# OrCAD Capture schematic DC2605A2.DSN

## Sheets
1 PAGE3: size B; title: HIGH EFFICIENCY, POLY-PHASE SYNCHRONOUS BUCK; rev: 2; company: TM; note: CONVERTER WITH POWER SYSTEM MANAGEMENT
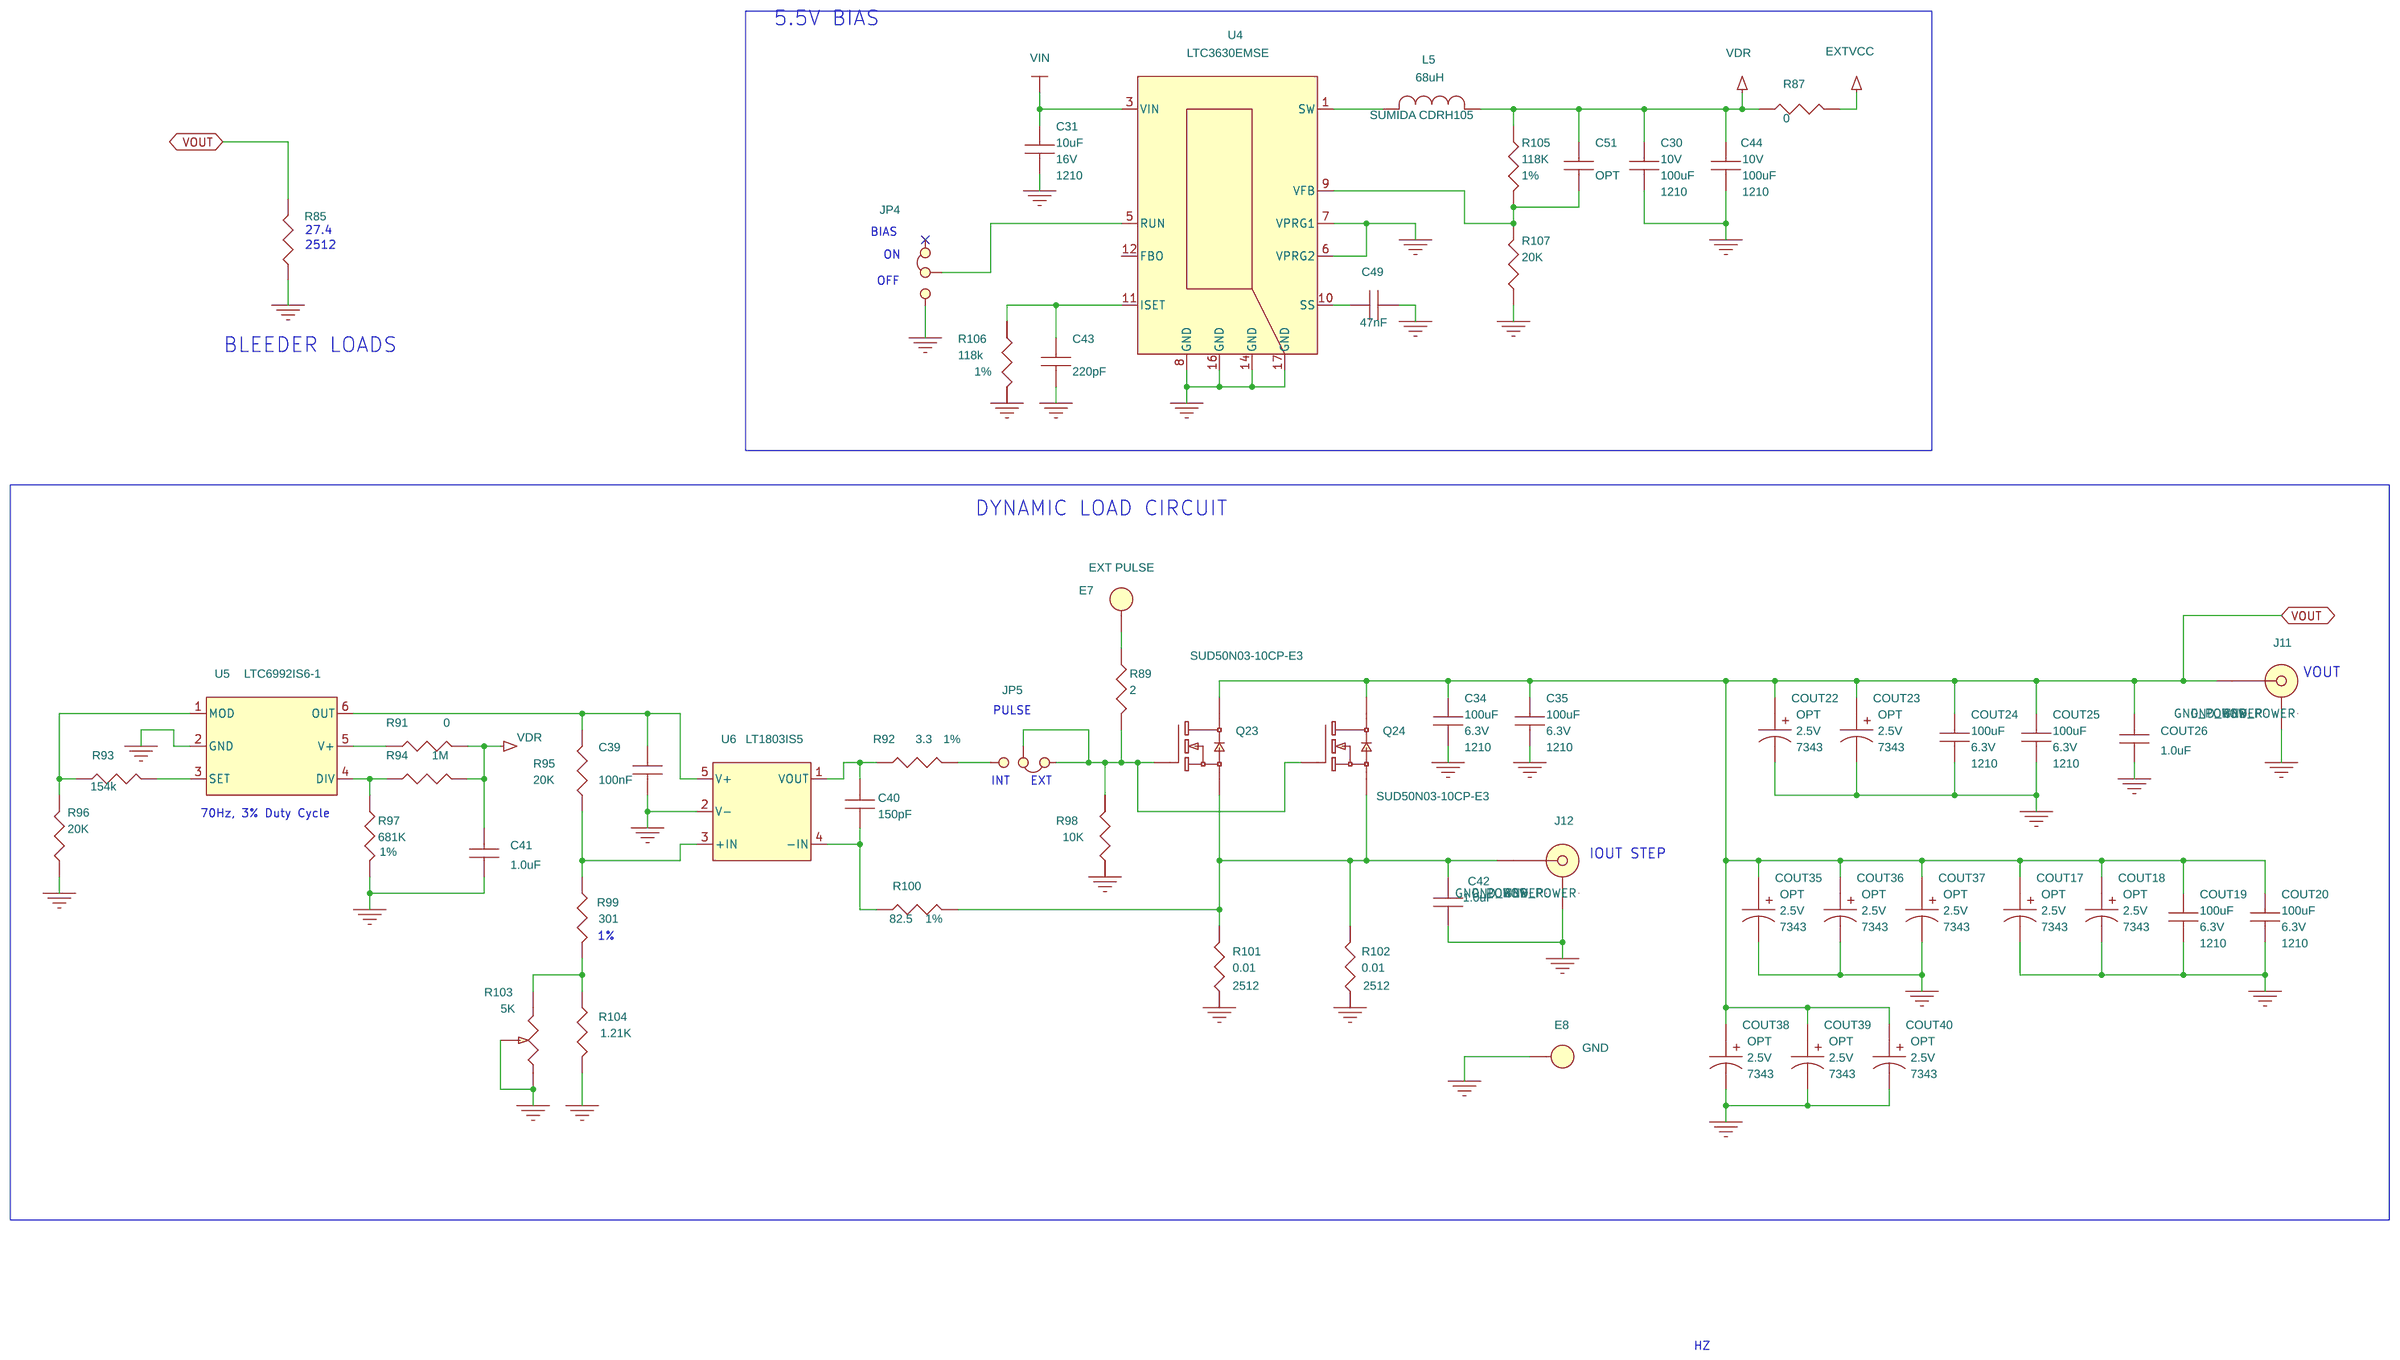
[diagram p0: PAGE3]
2 PAGE1: size Custom
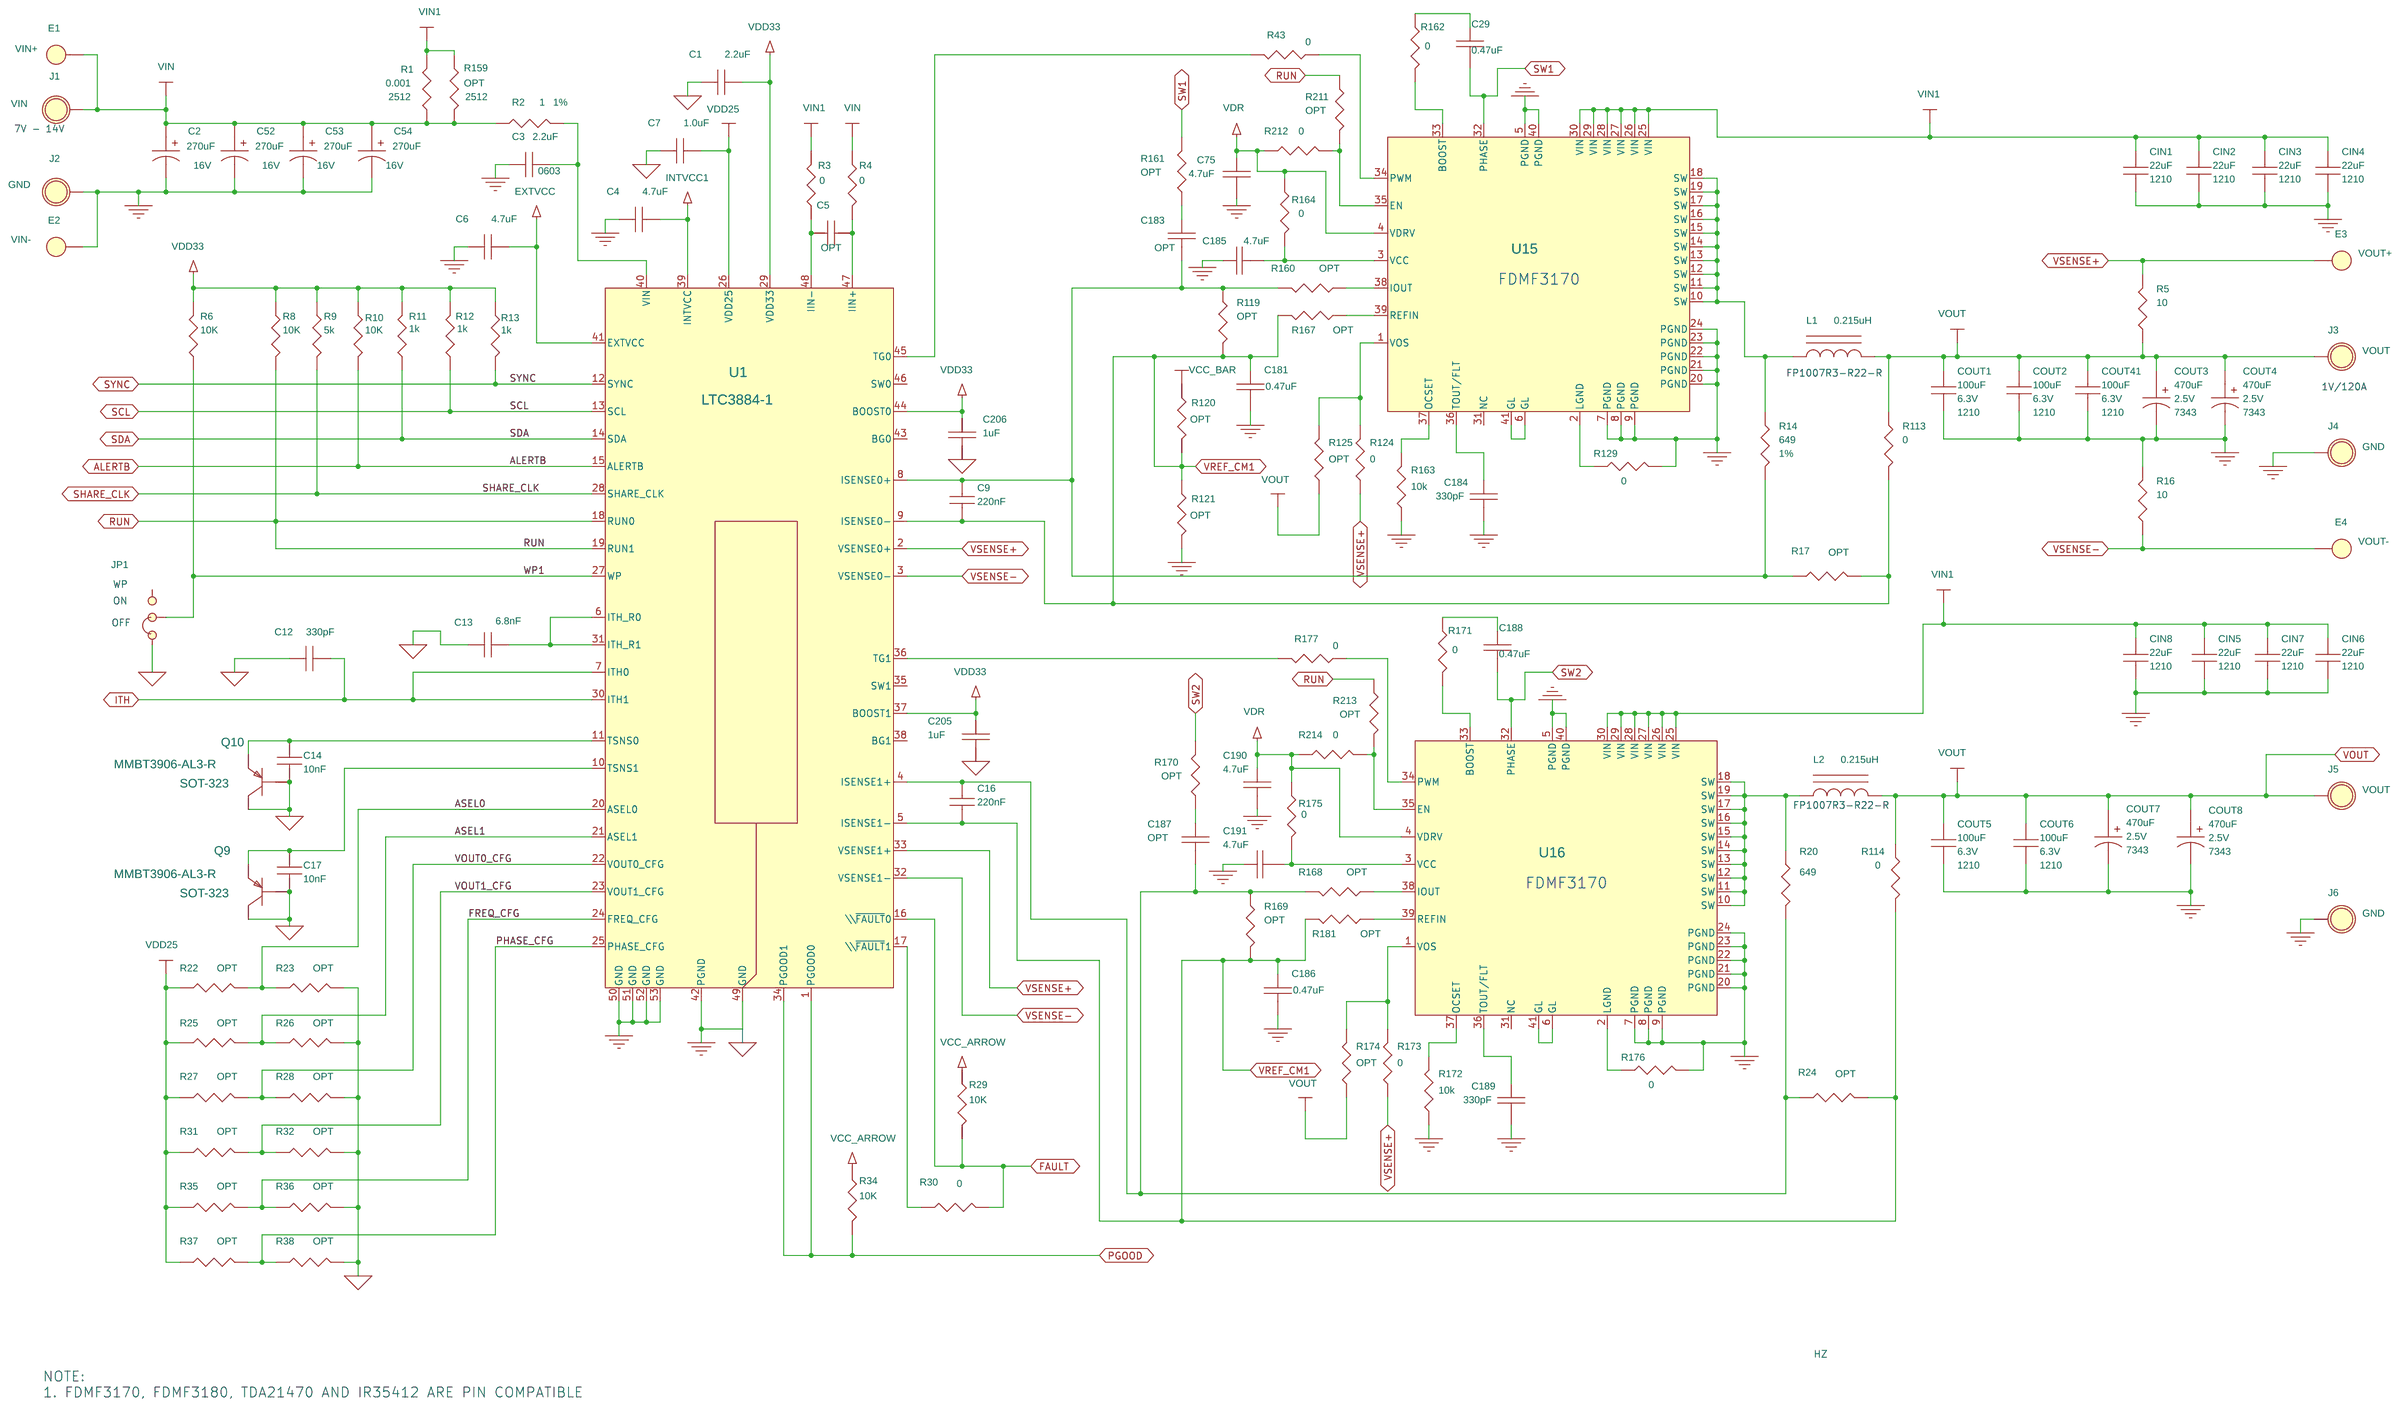
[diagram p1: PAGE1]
3 PAGE2: size Custom
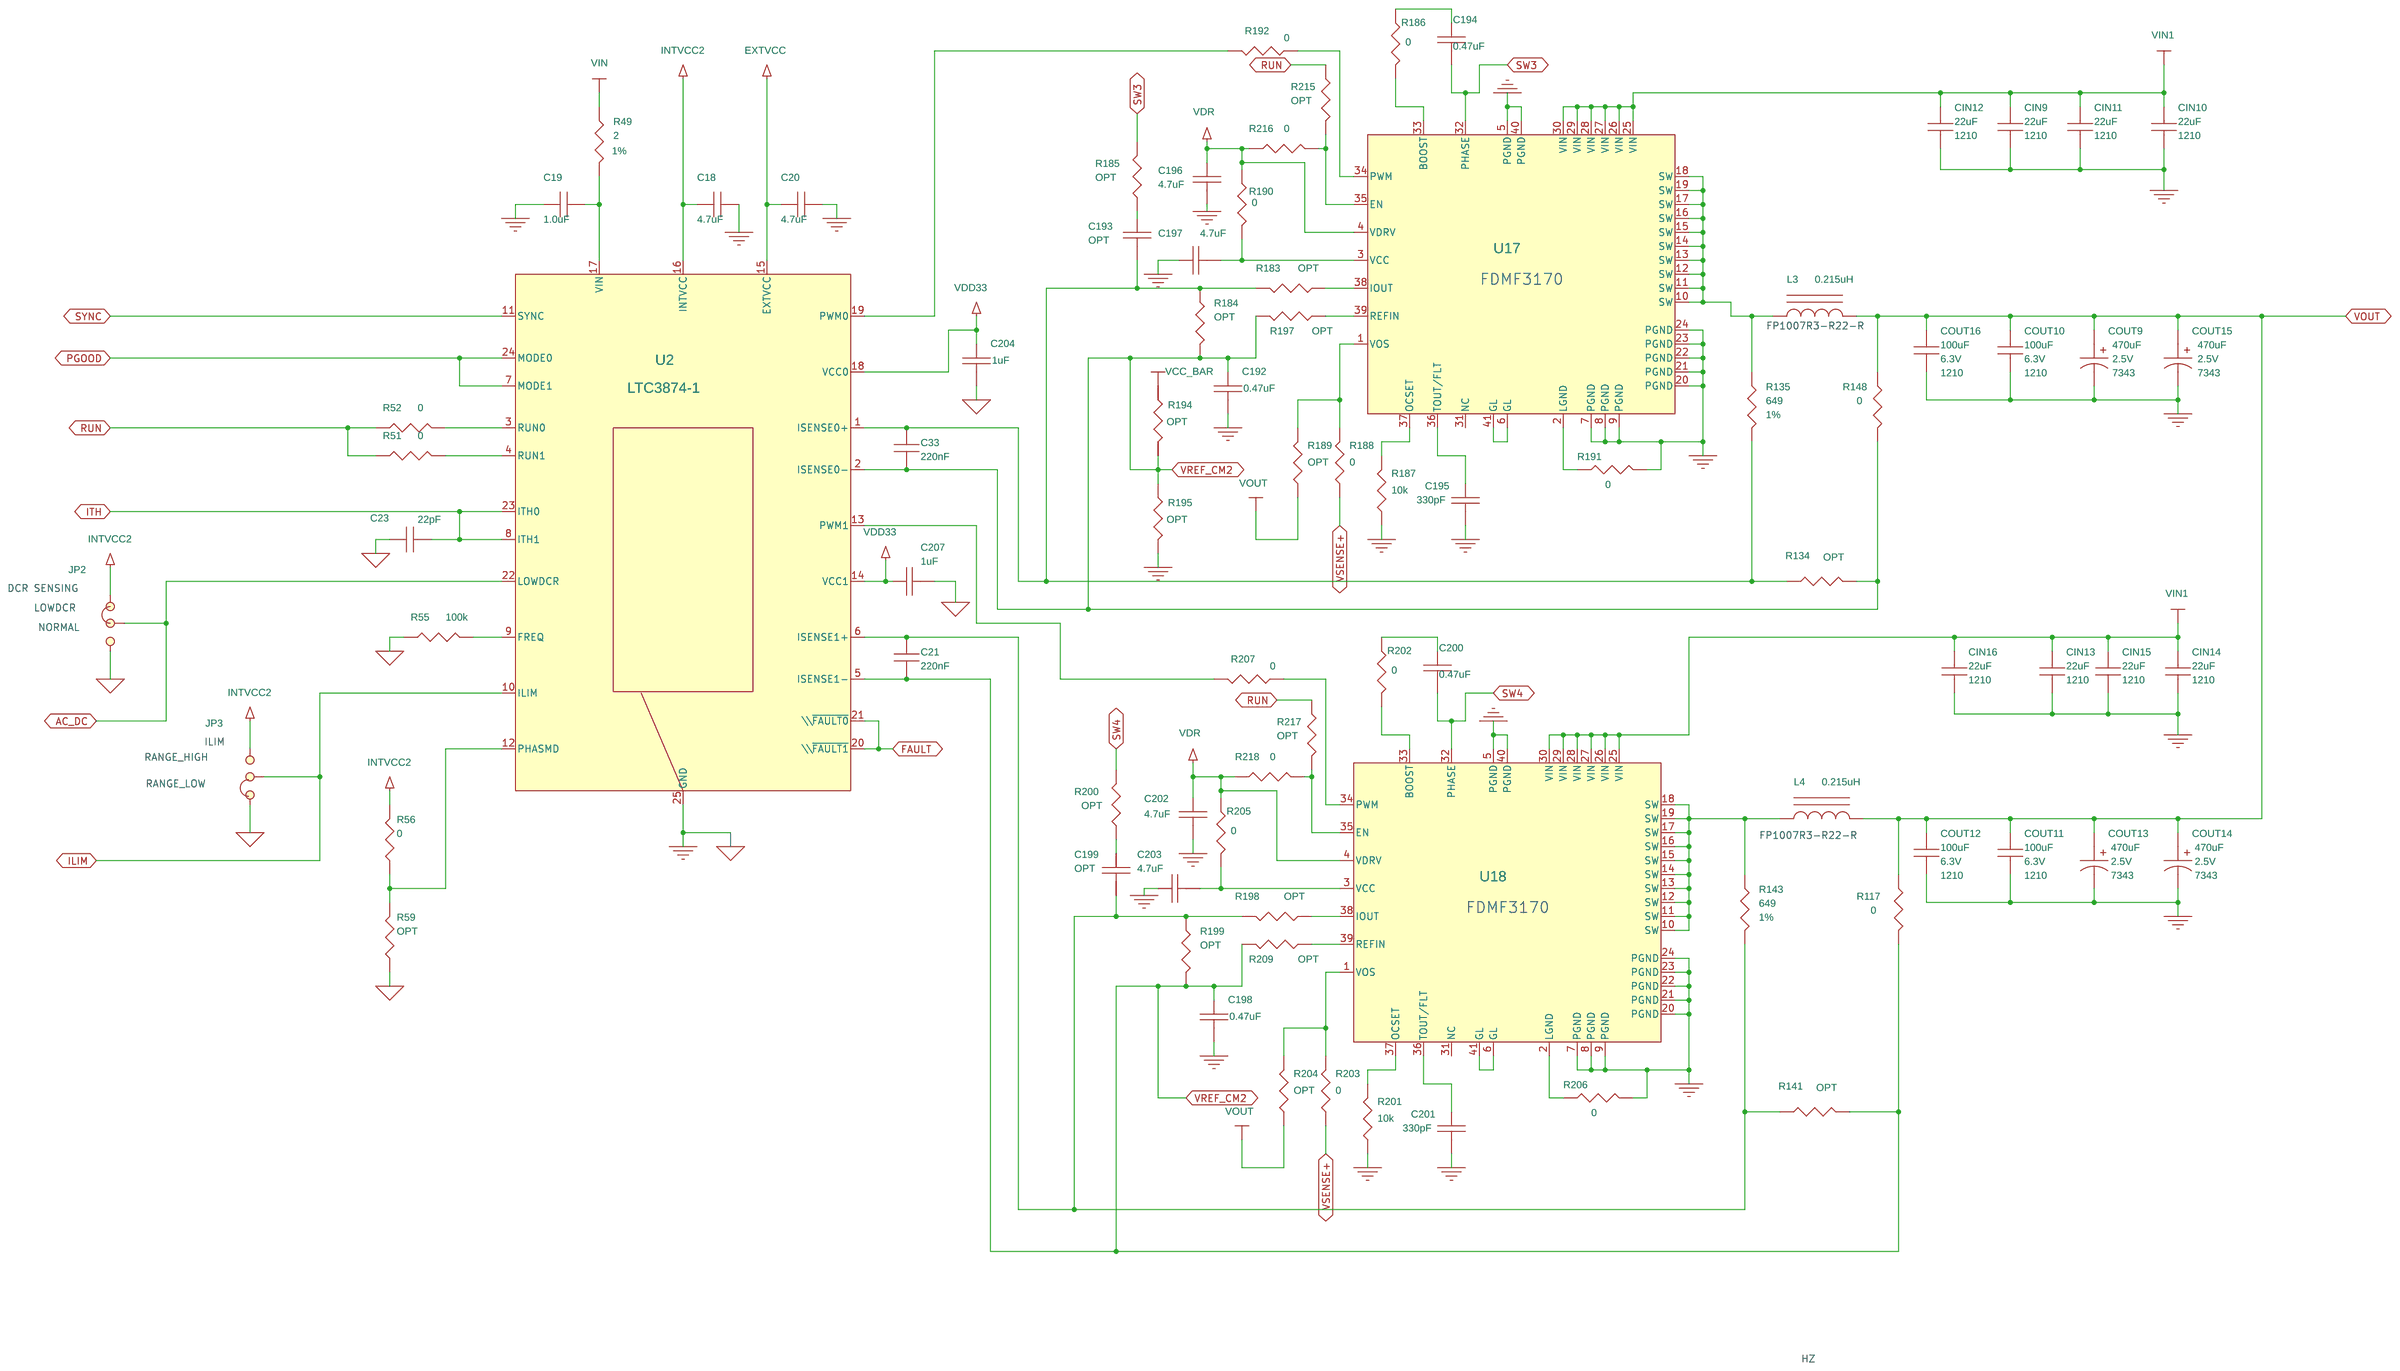
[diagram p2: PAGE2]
4 PAGE4: size B
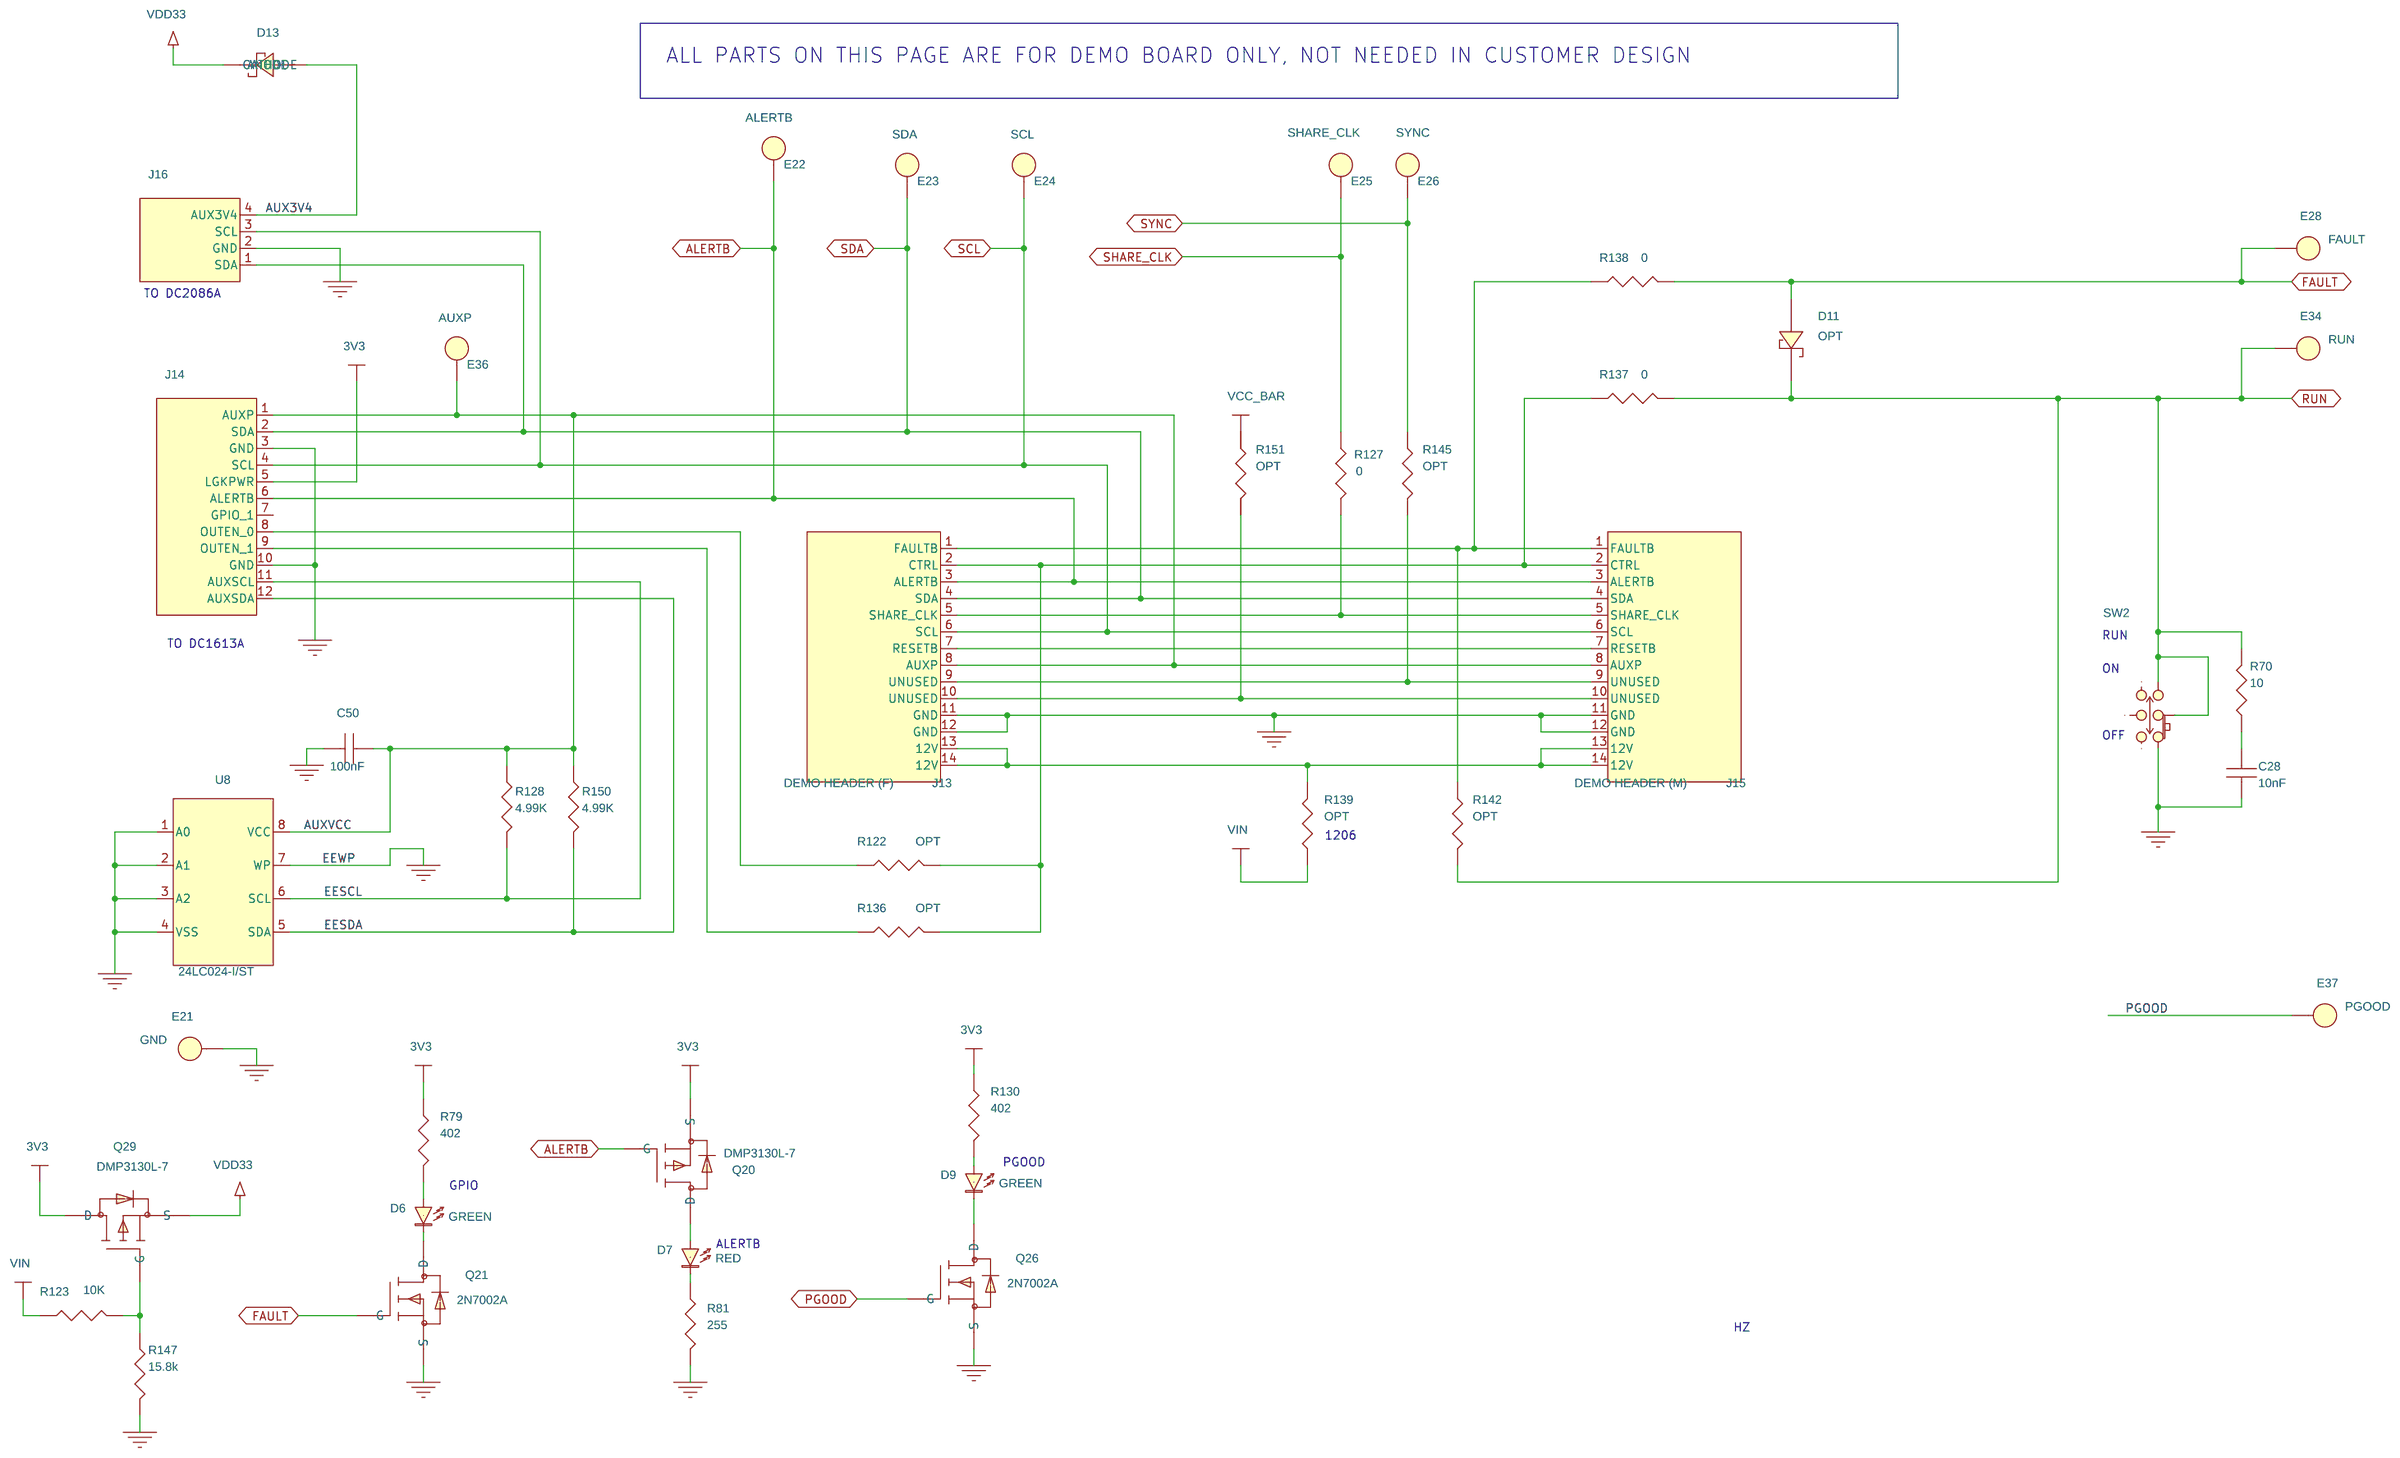
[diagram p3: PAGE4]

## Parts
sheet PAGE1
C1  2.2uF  [0603]
C2  270uF  [CAP\SAN\OSCON\SVF12]
C3  2.2uF  [0603]
C4  4.7uF  [0603]
C5  OPT  [0603]
C6  4.7uF  [0603]
C7  1.0uF  [0603]
C9  220nF  [0603]
C12  330pF  [0603]
C13  6.8nF  [0603]
C14  10nF  [0603]
C16  220nF  [0603]
C17  10nF  [0603]
C29  0.47uF  [0402]
C52  270uF  [CAP\SAN\OSCON\SVF12]
C53  270uF  [CAP\SAN\OSCON\SVF12]
C54  270uF  [CAP\SAN\OSCON\SVF12]
C75  4.7uF  [0402]
C181  0.47uF  [0402]
C183  OPT  [0402]
C184  330pF  [0402]
C185  4.7uF  [0402]
C186  0.47uF  [0402]
C187  OPT  [0402]
C188  0.47uF  [0402]
C189  330pF  [0402]
C190  4.7uF  [0402]
C191  4.7uF  [0402]
C205  1uF  [0402]
C206  1uF  [0402]
CIN1  22uF  [1210]
CIN2  22uF  [1210]
CIN3  22uF  [1210]
CIN4  22uF  [1210]
CIN5  22uF  [1210]
CIN6  22uF  [1210]
CIN7  22uF  [1210]
CIN8  22uF  [1210]
COUT1  100uF  [1210]
COUT2  100uF  [1210]
COUT3  470uF  [7343]
COUT4  470uF  [7343]
COUT5  100uF  [1210]
COUT6  100uF  [1210]
COUT7  470uF  [7343]
COUT8  470uF  [7343]
COUT41  100uF  [1210]
E1  VIN+  [TP\MMX\2501-2]
E2  VIN-  [TP\MMX\2501-2]
E3  VOUT+  [TP\MMX\2501-2]
E4  VOUT-  [TP\MMX\2501-2]
J1  BANANA SMALL  [CON\LUG\10]
J2  BANANA SMALL  [CON\LUG\10]
J3  BANANA SMALL  [CON\LUG\10]
J4  BANANA SMALL  [CON\LUG\10]
J5  BANANA SMALL  [CON\LUG\10]
J6  BANANA SMALL  [CON\LUG\10]
JP1  JP3X1/079\NO\12  [SIP\3P\2MM]
L1  0.215uH  [fp1007]
L2  0.215uH  [fp1007]
Q9  MMBT3906-AL3-R  [SOT-323]
Q10  MMBT3906-AL3-R  [SOT-323]
R1  0.001  [2512]
R2  1  [0603]
R3  0  [0603]
R4  0  [0603]
R5  10  [0603]
R6  10K  [0603]
R8  10K  [0603]
R9  5k  [0603]
R10  10K  [0603]
R11  1k  [0603]
R12  1k  [0603]
R13  1k  [0603]
R14  649  [0603]
R16  10  [0603]
R17  OPT  [0603]
R20  649  [0603]
R22  OPT  [0603]
R23  OPT  [0603]
R24  OPT  [0603]
R25  OPT  [0603]
R26  OPT  [0603]
R27  OPT  [0603]
R28  OPT  [0603]
R29  10K  [0603]
R30  0  [0603]
R31  OPT  [0603]
R32  OPT  [0603]
R34  10K  [0603]
R35  OPT  [0603]
R36  OPT  [0603]
R37  OPT  [0603]
R38  OPT  [0603]
R43  0  [0402]
R113  0  [0603]
R114  0  [0603]
R119  OPT  [0402]
R120  OPT  [0402]
R121  OPT  [0402]
R124  0  [0402]
R125  OPT  [0402]
R129  0  [0402]
R159  OPT  [2512]
R160  OPT  [0402]
R161  OPT  [0402]
R162  0  [0402]
R163  10k  [0402]
R164  0  [0402]
R167  OPT  [0402]
R168  OPT  [0402]
R169  OPT  [0402]
R170  OPT  [0402]
R171  0  [0402]
R172  10k  [0402]
R173  0  [0402]
R174  OPT  [0402]
R175  0  [0402]
R176  0  [0402]
R177  0  [0402]
R181  OPT  [0402]
R211  OPT  [0402]
R212  0  [0402]
R213  OPT  [0402]
R214  0  [0402]
U1  LTC3884-1  [CQFN-48-5MMX6MM]
U15  LTC2248CUH  [IR35411]
U16  LTC2248CUH  [IR35411]
XJP1  SHUNT  [NONE]
sheet PAGE2
C18  4.7uF  [0603]
C19  1.0uF  [0603]
C20  4.7uF  [0603]
C21  220nF  [0603]
C23  22pF  [0603]
C33  220nF  [0603]
C192  0.47uF  [0402]
C193  OPT  [0402]
C194  0.47uF  [0402]
C195  330pF  [0402]
C196  4.7uF  [0402]
C197  4.7uF  [0402]
C198  0.47uF  [0402]
C199  OPT  [0402]
C200  0.47uF  [0402]
C201  330pF  [0402]
C202  4.7uF  [0402]
C203  4.7uF  [0402]
C204  1uF  [0402]
C207  1uF  [0402]
CIN9  22uF  [1210]
CIN10  22uF  [1210]
CIN11  22uF  [1210]
CIN12  22uF  [1210]
CIN13  22uF  [1210]
CIN14  22uF  [1210]
CIN15  22uF  [1210]
CIN16  22uF  [1210]
COUT9  470uF  [7343]
COUT10  100uF  [1210]
COUT11  100uF  [1210]
COUT12  100uF  [1210]
COUT13  470uF  [7343]
COUT14  470uF  [7343]
COUT15  470uF  [7343]
COUT16  100uF  [1210]
JP2  JP3X1/079\NO\12  [SIP\3P\2MM]
JP3  JP3X1/079\NO\12  [SIP\3P\2MM]
L3  0.215uH  [fp1007]
L4  0.215uH  [fp1007]
R49  2  [0603]
R51  0  [0603]
R52  0  [0603]
R55  100k  [0603]
R56  0  [0603]
R59  OPT  [0603]
R117  0  [0603]
R134  OPT  [0603]
R135  649  [0603]
R141  OPT  [0603]
R143  649  [0603]
R148  0  [0603]
R183  OPT  [0402]
R184  OPT  [0402]
R185  OPT  [0402]
R186  0  [0402]
R187  10k  [0402]
R188  0  [0402]
R189  OPT  [0402]
R190  0  [0402]
R191  0  [0402]
R192  0  [0402]
R194  OPT  [0402]
R195  OPT  [0402]
R197  OPT  [0402]
R198  OPT  [0402]
R199  OPT  [0402]
R200  OPT  [0402]
R201  10k  [0402]
R202  0  [0402]
R203  0  [0402]
R204  OPT  [0402]
R205  0  [0402]
R206  0  [0402]
R207  0  [0402]
R209  OPT  [0402]
R215  OPT  [0402]
R216  0  [0402]
R217  OPT  [0402]
R218  0  [0402]
U2  LTC3874-1  [UF_24_4MMX4MM]
U17  LTC2248CUH  [IR35411]
U18  LTC2248CUH  [IR35411]
XJP2  SHUNT  [NONE]
XJP3  SHUNT  [NONE]
sheet PAGE3
C30  100uF  [1210]
C31  10uF  [1210]
C34  100uF  [1210]
C35  100uF  [1210]
C39  100nF  [0603]
C40  150pF  [0603]
C41  1.0uF  [0603]
C42  1.0uF  [0603]
C43  220pF  [0603]
C44  100uF  [1210]
C49  47nF  [0603]
C51  OPT  [0603]
COUT17  OPT  [7343]
COUT18  OPT  [7343]
COUT19  100uF  [1210]
COUT20  100uF  [1210]
COUT22  OPT  [7343]
COUT23  OPT  [7343]
COUT24  100uF  [1210]
COUT25  100uF  [1210]
COUT26  1.0uF  [0603]
COUT35  OPT  [7343]
COUT36  OPT  [7343]
COUT37  OPT  [7343]
COUT38  OPT  [7343]
COUT39  OPT  [7343]
COUT40  OPT  [7343]
E7  EXT PULSE  [TP\MMX\2501-2]
E8  GND  [TP\MMX\2501-2]
J11  XXX  [BNC]
J12  XXX  [BNC]
JP4  JP3X1/079\NO\12  [SIP\3P\2MM]
JP5  JP3X1/079\NO\12  [SIP\3P\2MM]
L5  68uH  [IND\SUMIDA\CDRH105R\12X12]
Q23  SUD50N03-10CP-E3  [TO-252]
Q24  SUD50N03-10CP-E3  [TO-252]
R85  OPT  [2512]
R87  0  [0603]
R89  2  [0603]
R91  0  [0603]
R92  3.3  [0603]
R93  154k  [0603]
R94  1M  [0603]
R95  20K  [0603]
R96  20K  [0603]
R97  681K  [0603]
R98  10K  [0603]
R99  301  [0603]
R100  82.5  [0603]
R101  0.01  [2512]
R102  0.01  [2512]
R103  5K  [BOURNS_3386P]
R104  1.21K  [0603]
R105  118K  [0603]
R106  118k  [0603]
R107  20K  [0603]
U4  LTC3630EMSE  [MSE-16L(12)]
U5  LTC6992IS6-1  [LT_S6]
U6  LT1803IS5  [LT_S5]
XJP4  SHUNT  [NONE]
XJP5  SHUNT  [NONE]
sheet PAGE4
C28  10nF  [0603]
C50  100nF  [0603]
D6  GREEN  [LED_0603]
D7  RED  [LED_0603]
D9  GREEN  [LED_0603]
D11  OPT  [SOD323]
D13  DIODE SCHOTTKY  [SOD882]
E21  GND  [TP\MMX\2501-2]
E22  ALERTB  [TP\MMX\2501-2]
E23  SDA  [TP\MMX\2501-2]
E24  SCL  [TP\MMX\2501-2]
E25  SHARE_CLK  [TP\MMX\2501-2]
E26  SYNC  [TP\MMX\2501-2]
E28  FAULT  [TP\MMX\2501-2]
E34  RUN  [TP\MMX\2501-2]
E36  AUXP  [TP\MMX\2501-2]
E37  PGOOD  [TP\MMX\2501-2]
J13  DEMO HEADER (F)  [NPPN072FJFN-RC]
J14  HD2X6-079  [HD2X6-079-MOLEX]
J15  DEMO HEADER (M)  [NPPN072FJFN]
J16  HD2X6-079-PMBUS_0  [CON\HRS\DF3A-4P-2DSA]
Q20  DMP3130L-7  [SOT23]
Q21  2N7002A  [SOT23]
Q26  2N7002A  [SOT23]
Q29  DMP3130L-7  [SOT23]
R70  10  [0603]
R79  402  [0603]
R81  255  [0603]
R122  OPT  [0603]
R123  10K  [0603]
R127  0  [0603]
R128  4.99K  [0603]
R130  402  [0603]
R136  OPT  [0603]
R137  0  [0603]
R138  0  [0603]
R139  OPT  [1206]
R142  OPT  [0603]
R145  OPT  [0603]
R147  15.8k  [0603]
R150  4.99K  [0603]
R151  OPT  [0603]
SW2  JP3X1/079\NO\12  [JS202011]
U8  24LC024-I/ST  [TSSOP-8_4.4MM]

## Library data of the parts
C1 = CAP_NP: CAP, 0603 2.2uF 20% 6.3V X5R; Part Number: TAIYO YUDEN JMK105BJ225MV-T; Volts/Amps/Watts: 50V
C2 C52-C54 = CAPR12X5_0: CAP, 270uF 20% 16V OSCON; Component: cap; Manufacturer: SANYO; Part Number: PANASONIC 16SVPC270M; Tolerance: 20%; Type: OS-CON; Volts/Amps/Watts: 16V
C3 = CAP_NP_0: CAP, 0805 2.2uF 10% 16V X7R; Part Number: MURATA GRM21BR71C225KA12L; VOLTAGE: 16V
C4 C6 C18 C20 = CAP_NP: CAP, 0603 4.7uF 10% 10V X5R; Part Number: AVX 0603ZD475KAT2A
C5 C51 = CAP_NP: CAP, 0603 OPTION; Part Number: OPTION
C7 C19 C41 COUT26 = CAP_NP: CAP, 0603 1uF 20% 25V X5R; Part Number: AVX 06033D105KAT2A
C9 C16 C21 C33 = CAP_NP: CAP, 0603 220nF 10% 25V X7R; Part Number: TDK C1608X7R1E224K
C12 = CAP_NP: CAP, 0603 330pF 5% 50V C0G; Part Number: MURATA GRM1885C1H331JD01D
C13 = CAP_NP: CAP, 0603 6.8nF 10% 50V X7R; Part Number: MURATA GRM188R71H682KA01B
C14 C17 C28 = CAP_NP: CAP, 0603 10nF 10% 25V X7R; Part Number: AVX 06033C103KAT2A
C29 C183 C187 C188 C193 C194 C199 C200 C205-C207 = CAP_4: CAP, 0402 0.47uF 10% 16V X5R; Component: cap; Manufacturer: Taiyo Yuden; Manufacturer P/N: LMK212B7475KG-T; Part Number: AVX 0402YD473JAT; Tolerance: 10%; Type: cer 0805 X7R; Vendor: Digikey; Vendor P/N: 587-1442-1-ND; Volts/Amps/Watts: 10V
C75 C185 C190 C191 C196 C197 C202 C203 = CAP_4: CAP, 0603 4.7uF 20% 10V X5R; Component: cap; Manufacturer: Taiyo Yuden; Manufacturer P/N: LMK212B7475KG-T; Part Number: TAIYO YUDEN LMK107BJ475KA-T; Tolerance: 10%; Type: cer 0805 X7R; Vendor: Digikey; Vendor P/N: 587-1442-1-ND; Volts/Amps/Watts: 10V
C181 C186 C192 C198 C204 = CAP_3: CAP, 0402 0.1uF 10% 16V X7R; Manufacturer: TDK; Manufacturer P/N: C1608X7R1H104K; Part Number: AVX 0402YC103KAT2A; Tolerance: 10%; Type: cer 0603 X7R; Vendor: Digikey; Vendor P/N: 445-1314-1-ND; Volts/Amps/Watts: 16V
C184 C189 C195 C201 = CAP_4: CAP, 0402 0.1uF 10% 16V X7R; Component: cap; Manufacturer: Taiyo Yuden; Manufacturer P/N: LMK212B7475KG-T; Part Number: AVX 0402YC103KAT2A; Tolerance: 10%; Type: cer 0805 X7R; Vendor: Digikey; Vendor P/N: 587-1442-1-ND; Volts/Amps/Watts: 16V
CIN1-CIN16 = CAP_NP_0: CAP, 1210 22uF 10% 25V X7R; Part Number: MURATA GRM32ER71E226KE15L; VOLTAGE: 50V; Volts/Amps/Watts: 6.3V
C34 C35 COUT1 COUT2 COUT5 COUT6 COUT10-COUT12 COUT16 COUT19 COUT20 COUT24 COUT25 COUT41 = CAP_NP_0: CAP, 1210 100uF 20% 6.3V X5R; Part Number: TDK C3225X5R0J107M; VOLTAGE: 50V; Volts/Amps/Watts: 6.3V
COUT3 COUT4 COUT7-COUT9 COUT13-COUT15 COUT17 COUT18 COUT22 COUT23 COUT35-COUT40 = t510x337k010as: CAP, 7343 470uF 20% 2.5V TANT. POLYMER; 1st Part Field: 2.5V; 3rd Part Field: POSCAP; Part Number: PANASONIC ETPF470M5H
E1-E4 E7 E8 E21-E26 E28 E34 E36 E37 = E_0: TURRET; Part Number: MILL MAX 2501-2-00-80-00-00-07-0
J1 = BANANA_SMALL_0: STUD, TEST PIN; Component: conn; Label: VIN; Part Number: PEM KFH-032-10
J2 J4 J6 = BANANA_SMALL_0: STUD, TEST PIN; Component: conn; Label: GND; Part Number: PEM KFH-032-10
J3 J5 = BANANA_SMALL_0: STUD, TEST PIN; Component: conn; Label: VOUT; Part Number: PEM KFH-032-10
JP1-JP5 = JP3X1_079_NO_12_1: HEADER, SINGLE ROW 3PIN; Part Number: SAMTEC TMM-103-02-L-S
L1-L4 = INDUCTOR_IRON: IND, 0.25uH; Part Number: WURTH ELEKTRONIK 744301025
Q9 Q10 = MMBT3906_SOT_0: XSTR, PNP GENERAL PURPOSE; Part Number: DIODES INC. MMST3906-7-F
R1 = RES0603_0: RES, 2512 0.001 OHMS 1% 1W; Label: 2; Manufacturer: Rohm; Manufacturer P/N: RHM0.0GCT-ND; Part Number: VISHAY WSL25121L000FEA; Vendor: Digikey; Vendor P/N: RHM0.0GCT-ND; Volts/Amps/Watts: 0.1W
R2 = RES0603_0: RES, 0603 1 OHMS 1% 1/10W; Component: res; Label: <label>; Manufacturer: Panasonic; Manufacturer P/N: ERJ-3EKF5901V; Part Number: VISHAY CRCW06031R00FNEA; Tolerance: 1%; Vendor: Digikey; Vendor P/N: P5.90KHCT-ND; Volts/Amps/Watts: 0.1W
R3 R127 = RES0603_0: RES, 0603 0 OHMS JUMPER; Manufacturer: Rohm; Manufacturer P/N: RHM0.0GCT-ND; Part Number: VISHAY CRCW06030000Z0EA; Tolerance: 5%; Vendor: Digikey; Vendor P/N: RHM0.0GCT-ND; Volts/Amps/Watts: 0.1W
R4 = RES0603_0: RES, 0603 0 OHMS JUMPER; Manufacturer: ROHM; Manufacturer P/N: MCR03EZPFX1002; Part Number: VISHAY CRCW06030000Z0EA; Vendor: Digikey; Vendor P/N: RHM10.0KHCT-ND; Volts/Amps/Watts: 0.1W
R5 = RES0603_0: RES, 0603 10 OHMS 1% 0.1W; Manufacturer: Yageo; Manufacturer P/N: RC0603JR-070RL; Part Number: VISHAY CRCW060310R0FKEA; Tolerance: 1%; Vendor: Digikey; Vendor P/N: 311-0.0GRCT-ND; Volts/Amps/Watts: 0.1W
R6 R56 = RES0603_0: RES, 0603 10K OHMS 5% 0.1W; Manufacturer: Panasonic; Manufacturer P/N: ERJ-3EKF2002V; Part Number: VISHAY CRCW060310K0JNEA; Vendor: Digikey; Vendor P/N: P20.0KHCT-ND; Volts/Amps/Watts: 0.1W
R8 R10 = RES0603_0: RES, 0603 10K OHMS 5% 0.1W; Manufacturer: ROHM; Manufacturer P/N: MCR03EZPFX1002; Part Number: VISHAY CRCW060310K0JNEA; Vendor: Digikey; Vendor P/N: RHM10.0KHCT-ND; Volts/Amps/Watts: 0.1W
R9 = RES0603_0: RES, 0603 5k OHMS 5% 0.1W; Manufacturer: ROHM; Manufacturer P/N: MCR03EZPFX1002; Part Number: VISHAY CRCW06035K00JNED; Vendor: Digikey; Vendor P/N: RHM10.0KHCT-ND; Volts/Amps/Watts: 0.1W
R11-R13 = RES0603_0: RES, 0603 1K OHMS 5% 0.1W; Manufacturer: ROHM; Manufacturer P/N: MCR03EZPFX1002; Part Number: VISHAY CRCW06031K00JNEA; Vendor: Digikey; Vendor P/N: RHM10.0KHCT-ND; Volts/Amps/Watts: 0.1W
R14 R135 = R_1: RES, 0603 715 OHMS 1% 0.1W; %: 0.1%; Part Number: VISHAY CRCW0603715RFKEA; Tol: 1%
R16 = RES0603_0: RES, 0603 10 OHMS 1% 1/10W; Manufacturer: Yageo; Manufacturer P/N: RC0603JR-070RL; Part Number: VISHAY CRCW060310R0FKEA; Tolerance: 1%; Vendor: Digikey; Vendor P/N: 311-0.0GRCT-ND; Volts/Amps/Watts: 0.1W
R17 R24 R134 R141 = R_1: RES, 0603 OPTION; %: 0.1%; Part Number: OPTION
R20 R113 R114 R117 R148 = R_1: RES, 0603 0 OHMS JUMPER; %: 0.1%; Part Number: VISHAY CRCW06030000Z0EA; Tol: 1%
R22 R28 R32 R36 R38 = RES0603_0: RES, 0603 OPTION; Manufacturer: Panasonic; Manufacturer P/N: ERJ-3EKF2002V; Part Number: OPTION; Vendor: Digikey; Vendor P/N: P20.0KHCT-ND; Volts/Amps/Watts: 0.1W
R23 = RES0603_0: RES, 0603 OPTION; Manufacturer: Rohm; Manufacturer P/N: RHM0.0GCT-ND; Part Number: OPTION; Tolerance: 5%; Vendor: Digikey; Vendor P/N: RHM0.0GCT-ND; Volts/Amps/Watts: 0.1W
R25 = RES0603_0: RES, 0603 OPTION; Manufacturer: Panasonic; Manufacturer P/N: ERJ-3EKF5901V; Part Number: OPTION; Vendor: Digikey; Vendor P/N: P5.90KHCT-ND; Volts/Amps/Watts: 0.1W
R26 = RES0603_0: RES, 0603 OPTION; Manufacturer: Panasonic; Manufacturer P/N: ERJ-3EKF2002V; Part Number: OPTION; Tolerance: 5%; Vendor: Digikey; Vendor P/N: P20.0KHCT-ND; Volts/Amps/Watts: 0.1W
R27 = RES0603_0: RES, 0603 OPTION; Manufacturer: Panasonic; Manufacturer P/N: ERJ-3EKF1000V; Part Number: OPTION; Vendor: Digikey; Vendor P/N: P100HCT-ND; Volts/Amps/Watts: 0.1W
R29 R34 = RES0603_0: RES, 0603 10K OHMS 5% .01W; Manufacturer: Panasonic; Manufacturer P/N: ERJ-3EKF2002V; Part Number: VISHAY CRCW060310K0JNEA; Vendor: Digikey; Vendor P/N: P20.0KHCT-ND; Volts/Amps/Watts: 0.1W
R30 = R_1: RES, 0603 0 OHMS JUMPER; %: 0.1%; Part Number: VISHAY CRCW06030000Z0EA
R31 = RES0603_0: RES, 0603 OPTION; Manufacturer: Panasonic; Manufacturer P/N: ERJ-3EKF1021V; Part Number: OPTION; Vendor: Digikey; Vendor P/N: P1.02KHCT-ND; Volts/Amps/Watts: 0.1W
R35 R37 = RES0603_0: RES, 0603 OPTION; Manufacturer: ROHM; Manufacturer P/N: MCR03EZPFX1002; Part Number: OPTION; Vendor: Digikey; Vendor P/N: RHM10.0KHCT-ND; Volts/Amps/Watts: 0.1W
R43 R119 R124 R125 R160 R161 R163 R167-R170 R172-R174 R177 R181 R183-R185 R187-R189 R192 R197-R201 R203 R204 R207 R209 = RES0603_9: RES, 0402 2 OHMS 1% 1/16W; Manufacturer: Panasonic; Part Number: VISHAY CRCW04022R00FNEA; Vendor: Digikey; Vendor P/N: P100HCT-ND; Volts/Amps/Watts: 0.1W
R120 R121 R194 R195 = RES0603_9: RES, 0402 4.53k OHMS 1% 1/16W; Component: res; Label: <label>; Manufacturer: Panasonic; Manufacturer P/N: ERJ-3EKF5901V; Part Number: VISHAY CRCW04024K53FKED; Tolerance: 1%; Vendor: Digikey; Vendor P/N: P5.90KHCT-ND; Volts/Amps/Watts: 0.1W
R129 R162 R164 R171 R175 R176 R186 R190 R191 R202 R205 R206 R211-R218 = RES0603_9: RES, 0402 0 OHM JUMPER; Manufacturer: Panasonic; Part Number: VISHAY CRCW04020000Z0EA; Vendor: Digikey; Vendor P/N: P100HCT-ND; Volts/Amps/Watts: 0.1W
R159 = RES0603_0: RES, 2512 OPTION; Label: 2; Manufacturer: Rohm; Manufacturer P/N: RHM0.0GCT-ND; Part Number: OPTION; Vendor: Digikey; Vendor P/N: RHM0.0GCT-ND; Volts/Amps/Watts: 0.1W
U1 = LTC3880-M0001_15: IC, DUAL OUTPUT STEP-DOWN CONTROLLER; Component: IC; Manufacturer: LTC; Manufacturer P/N: LTC3880_M0001; Part Number: LINEAR TECH. LTC3884EUK; Part Type: LTC3884EUK
U15-U18 = LTC_3
XJP1-XJP5 = SHUNT: Part Number: SAMTEC 2SN-BK-G
C23 = CAP_NP: CAP, 0603 22pF 5% 50V C0G; Part Number: MURATA GRM1885C1H220JA01B
R49 = RES0603_0: RES, 0603 2 OHMS 1% 0.1W; Component: res; Label: <label>; Manufacturer: Panasonic; Manufacturer P/N: ERJ-3EKF5901V; Part Number: VISHAY CRCW06032R00FNEA; Tolerance: 1%; Vendor: Digikey; Vendor P/N: P5.90KHCT-ND; Volts/Amps/Watts: 0.1W
R51 R52 R91 = RES0603_0: RES, 0603 0 OHMS JUMPER; Component: res; Label: <label>; Manufacturer: Panasonic; Manufacturer P/N: ERJ-3EKF5901V; Part Number: VISHAY CRCW06030000Z0EA; Tolerance: 1%; Vendor: Digikey; Vendor P/N: P5.90KHCT-ND; Volts/Amps/Watts: 0.1W
R55 = RES0603_0: RES, 0603 100K OHMS 5% 0.1W; Component: res; Label: <label>; Manufacturer: Panasonic; Manufacturer P/N: ERJ-3EKF5901V; Part Number: VISHAY CRCW0603100KJNEA; Tolerance: 1%; Vendor: Digikey; Vendor P/N: P5.90KHCT-ND; Volts/Amps/Watts: 0.1W
R59 R95 R96 R107 = RES0603_0: RES, 0603 20K OHMS 5% 0.1W; Manufacturer: Panasonic; Manufacturer P/N: ERJ-3EKF2002V; Part Number: VISHAY CRCW060320K0JNEA; Vendor: Digikey; Vendor P/N: P20.0KHCT-ND; Volts/Amps/Watts: 0.1W
R143 = R_1: RES, 0603 715 OHMS 1% 0.1W; %: 1%; Part Number: VISHAY CRCW0603715RFKEA; Tol: 1%
U2 = LTC3880-M0001_11: IC, STEP-DOWN SLAVE CONTROLLER; Component: IC; Manufacturer: LTC; Manufacturer P/N: LTC3880_M0001; Part Number: LINEAR TECH.LTC3874EUFD; Part Type: LTC3880EUF
C30 C44 = CAP_NP: CAP, 1210 100uF 20% 10V X5R; 1ST PART FIELD: 10V; Part Number: TAIYO YUDEN LMK325ABJ107MM-T
C31 = CAP_NP_1: CAP, 1210 10uF 10% 16V X7R; Part Number: MURATA GRM32DR71C106KA01; Voltage: 16V
C39 C50 = CAP_NP: CAP, 0603 100nF 20% 16V X7R; Part Number: AVX 0603YC104MAT2A
C40 = CAP_NP: CAP, 0603 150pF 5% 50V NPO; Part Number: AVX 06035A151JAT2A
C42 = CAP_NP_1: CAP, 0603 1uF 20% 25V X5R; Part Number: AVX 06033D105KAT2A
C43 = CAP_NP: CAP, 0603 220pF 10% 50V X7R; Part Number: AVX 06035C221KAT2A
C49 = CAP_NP: CAP, 0603 47nF 10% 25V X7R; Part Number: AVX 06033C473KAT
J11 = BNC5-SCH_15: CONN, BNC, 5 PINS; Part Number: CONNEX 112404; Pin Numbers Visible: <Pin Numbers Visible>
J12 = BNC5-SCH_16: CONN, BNC, 5 PINS; Part Number: CONNEX 112404
L5 = IND-TDK-VLF: IND, 68uH; 5TH PART FIELD: SUMIDA CDRH105; Part Number: SUMIDA CDRH105RNP-680N
Q23 Q24 = 2N7002_13: XSTR, MOSFET, N-CHANNEL 30V; Part Number: VISHAY SUD50N03-10CP-E3
R85 = RES0603_5: RES, 2512 OPTION; Label: 1W; Manufacturer: VISHAY; Manufacturer P/N: CRCW251230R0JNEG; Part Number: OPTION; Tolerance: 5%
R87 = RESISTOR_1: RES, 0603 OPTION; Part Number: OPTION
R89 = RES0603_0: RES, 0603 2 OHMS 5% 0.1W; Manufacturer: ROHM; Manufacturer P/N: MCR03EZPFX4991; Part Number: VISHAY CRCW06032R00JNED; Vendor: Digikey; Vendor P/N: RHM4.99KHCT-ND; Volts/Amps/Watts: 0.1w
R92 = RES0603_0: RES, 0603 3.3 OHMS 1% 0.1W; Manufacturer: ROHM; Manufacturer P/N: MCR03EZPFX4991; Part Number: VISHAY CRCW06033R30FNEA; Tolerance: 1%; Vendor: Digikey
R93 = RES0603_0: RES, 0603 154K OHMS 5% 0.1W; Component: res; Label: <label>; Manufacturer: Panasonic; Manufacturer P/N: ERJ-3EKF5901V; Part Number: VISHAY CRCW0603154KJNEA; Tolerance: 1%; Vendor: Digikey; Vendor P/N: P5.90KHCT-ND; Volts/Amps/Watts: 0.1W
R94 = RES0603_0: RES, 0603 1M OHMS 5% 0.1W; Label: OPT 0; Manufacturer: Rohm; Manufacturer P/N: RHM0.0GCT-ND; Part Number: VISHAY CRCW06031M00JNEA; Vendor: Digikey
R97 = RES0603_0: RES, 0603 681K OHMS 1% 0.1W; Manufacturer: ROHM; Manufacturer P/N: MCR03EZPFX4991; Part Number: VISHAY CRCW0603681KFEA; Tolerance: 1%
R98 = RES0603_0: RES, 0603 10K OHMS 5% 0.1W; Manufacturer: Panasonic; Manufacturer P/N: ERJ-3EKF2002V; Part Number: VISHAY CRCW060310K0JNEA; Vendor: Digikey
R99 = RES0603_0: RES, 0603 301 OHMS 1% 0.1W; Manufacturer: ROHM; Manufacturer P/N: MCR03EZPFX4991; Part Number: VISHAY CRCW0603301RFKEA; Vendor: Digikey; Vendor P/N: RHM4.99KHCT-ND; Volts/Amps/Watts: 0.1w
R100 = RES0603_0: RES, 0603 82.5 OHMS 5% 0.1W; Manufacturer: ROHM; Manufacturer P/N: MCR03EZPFX4991; Part Number: VISHAY CRCW060382R5FKEA; Tolerance: 1%; Vendor: Digikey
R101 R102 = RES0603_5: RES, 2512 0.01 OHMS 1% 1W; Label: 1W; Manufacturer: VISHAY; Manufacturer P/N: CRCW251230R0JNEG; Part Number: VISHAY WSL2512R0100FEA; Tolerance: 5%
R103 = POT: RES, VARIABLE 5K; Part Number: BOURNS 3386P-1-502-LF
R104 = RES0603_0: RES, 0603 1.21K OHMS 1% 0.1W; Manufacturer: ROHM; Manufacturer P/N: MCR03EZPFX4991; Part Number: VISHAY CRCW06031K21FKEA; Vendor: Digikey; Vendor P/N: RHM4.99KHCT-ND; Volts/Amps/Watts: 0.1w
R105 = RESISTOR_1: RES, 0603 118K OHM 1% 0.1W; Part Number: VISHAY CRCW0603118KFKEA; Tolerance: 1%
R106 = AAC-0603: RES, 0603 80.6k OHMS 1% 0.1W; 1ST PART FIELD: 1%; Part Number: VISHAY CRCW060380K6FKEA
U4 = LTC3630EMSE_0: IC, SYNCHRONOUS STEP-DOWN CONVERTER; Part Number: LINEAR TECH. LTC3630EMSE
U5 = LT1129CS8-3_1.3: IC, TIMER BLOX: VOLTAGE CONTROLLED (PWM); Part Number: LINEAR TECH. LTC6992IS6-1
U6 = LT1129CS8-3_2.3: IC, OP AMP; Part Number: LINEAR TECH. LT1803IS5
D6 D9 = DIODE-LED_2: LED, 0603 GREEN; Manufacturer: PANASONIC; Manufacturer P/N: LN1371SGTRP; Part Number: WURTH ELEKTRONIK 150060GS75000
D7 = DIODE-LED_2: LED, 0603 RED; Label: GREEN; Manufacturer: PANASONIC; Part Number: WURTH ELEKTRONIK 150060SS75000
D11 = DIODE_SCHOTTKY_9: DIODE, SCHOTTKY 30V, 100mA OPTION; Part Number: CENTRAL SEMI CMDSH-3-TR OPTION
D13 = DIODE_SCHOTTKY_0: DIODE, ULTRA LOW  SCHOTTKY RECTIEIER; Part Number: NXP SEMI. PMEG2005AEL,315
J13 = PMBUS_CONNECTOR20_3: CONN, SOCKET 14PIN  DUAL ROW R/A; Component: con; Manufacturer: Mill Max; Manufacturer P/N: 803-93-020-20-001; Part Number: SULLINSINC. NPPN072FJFN-RC; Part Type: HDR2X10RA; Type: conn  RA 20 dual row; Vendor: LTC; Vendor P/N: 803-93-020-20-001
J14 = HD2X6-079-PMBUS_2: HEADER, 12PIN 2mm STR DL; Label: DC1427A HEADER; Manufacturer: MOLEX; Manufacturer P/N: 87831-1220; Part Number: FCI 98414-G06-12ULF; Type: header 12POS 2MM VERT; Vendor: Digikey; Vendor P/N: WM18561-ND
J15 = PMBUS_HEADER20_3: HEADER, 14PIN DUAL ROW R/A; Component: con; Manufacturer: Mill Max; Manufacturer P/N: 802-40-020-20-0001; Part Number: MOLEX 87760-1416; Part Type: HDR_2X10_RA_REV; Type: header RA 20 dual row; Vendor: LTC; Vendor P/N: 802-40-020-20-001
J16 = HD2X6-079-PMBUS_4: HEADER, 4PIN 2mm STR DL; Manufacturer: Hirose; Part Number: HIROSE DF3A-4P-2DSA; Type: header 4POS 2MM VERT
Q20 Q29 = P-MOSFET: XSTR, P-CHANNEL DMOS FET; Part Number: DIODES INC. DMP3130L-7
Q21 Q26 = TRANSISTOR_0: XSTR, N-CHANNEL DMOS FET; Part Number: FAIRCHILD 2N7002A
R70 = RES0603_1: RES, 0603 10 OHMS 5% 0.1W; Manufacturer: Rohm; Manufacturer P/N: RHM0.0GCT-ND; Part Number: VISHAY CRCW060310R0JNEA; Tolerance: 5%; Vendor: Digikey; Vendor P/N: RHM0.0GCT-ND; Volts/Amps/Watts: 0.1W
R79 R130 = RES0603_0: RES, 0603 200 OHMS 5% 0.1W; Label: OPT 0; Manufacturer: Rohm; Manufacturer P/N: RHM0.0GCT-ND; Part Number: VISHAY CRCW0603200RJNEA; Tolerance: 5%; Vendor: Digikey; Vendor P/N: RHM0.0GCT-ND; Volts/Amps/Watts: 0.1W
R81 = RES0603_0: RES, 0603 127 OHMS 1% 0.1W; Label: OPT 0; Manufacturer: Rohm; Manufacturer P/N: RHM0.0GCT-ND; Part Number: VISHAY CRCW0603127RFKEA; Tolerance: 5%; Vendor: Digikey; Vendor P/N: RHM0.0GCT-ND; Volts/Amps/Watts: 0.1W
R122 = RES0603_3: RES, 0603 OPTION; Label: OPT 0; Manufacturer: Rohm; Manufacturer P/N: RHM0.0GCT-ND; Part Number: OPTION; Tolerance: 5%; Vendor: Digikey; Vendor P/N: RHM0.0GCT-ND; Volts/Amps/Watts: 0.1W
R123 = RES0603_11: RES, 0603 10K OHMS 5% 0.1W; Part Number: VISHAY CRCW060310K0JNEA
R128 R150 = RES0603_0: RES, 0603 4.99K OHMS 1% 0.1W; Manufacturer: ROHM; Manufacturer P/N: MCR03EZPFX4991; Part Number: VISHAY CRCW06034K99FKEA; Vendor: Digikey; Vendor P/N: RHM4.99KHCT-ND; Volts/Amps/Watts: 0.1w
R136 R142 R145 R151 = RES0603_0: RES, 0603 OPTION; Label: OPT 0; Manufacturer: Rohm; Manufacturer P/N: RHM0.0GCT-ND; Part Number: OPTION; Tolerance: 5%; Vendor: Digikey; Vendor P/N: RHM0.0GCT-ND; Volts/Amps/Watts: 0.1W
R137 R138 = RES0603_0: RES, 0603 0 OHMS JUMPER; Label: OPT 0; Manufacturer: Rohm; Manufacturer P/N: RHM0.0GCT-ND; Part Number: VISHAY CRCW06030000Z0EA; Tolerance: 5%; Vendor: Digikey; Vendor P/N: RHM0.0GCT-ND; Volts/Amps/Watts: 0.1W
R139 = RES0603_3: RES, 1206 OPTION; Label: OPT 0; Manufacturer: Rohm; Manufacturer P/N: RHM0.0GCT-ND; Part Number: OPTION; Tolerance: 5%; Vendor: Digikey; Vendor P/N: RHM0.0GCT-ND; Volts/Amps/Watts: 0.1W
R147 = RES0603_11: RES, 0603 15.8K OHMS 1% 0.1W; Part Number: VISHAY CRCW060315K8FKEA
SW2 = JP3X1_079_NO_12_3: SWITCH, SUBMINATURE SLIDE; Part Number: C&K JS202011CQN
U8 = 24LC025-I_SN: IC, SERIAL EEPROM; Manufacturer PN: 24LC025-I/ST; Part Number: MICROCHIP 24LC024-I/ST

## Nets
3V3: J14.5(LGKPWR) Q20.2(S) Q29.3(D) R79.1 R130.1 R151.1
GND_POWER: C2.2 C3.1 C4.1 C6.1 C18.2 C19.1 C20.2 C28.2 C30.2 C31.2 C34.2 C35.2 C39.2 C41.1 C42.1 C43.2 C44.2 C49.2 C50.2 C52.2 C53.2 C54.2 C75.2 C181.2 C184.2 C185.1 C186.2 C189.2 C190.2 C191.1 C192.2 C195.2 C196.2 C197.1 C198.2 C201.2 C202.2 C203.1 CIN1.2 CIN2.2 CIN3.2 CIN4.2 CIN5.2 CIN6.2 CIN7.2 CIN8.2 CIN9.2 CIN10.2 CIN11.2 CIN12.2 CIN13.2 CIN14.2 CIN15.2 CIN16.2 COUT1.2 COUT2.2 COUT3.2 COUT4.2 COUT5.2 COUT6.2 COUT7.2 COUT8.2 COUT9.2 COUT10.2 COUT11.2 COUT12.2 COUT13.2 COUT14.2 COUT15.2 COUT16.2 COUT17.2 COUT18.2 COUT19.2 COUT20.2 COUT22.2 COUT23.2 COUT24.2 COUT25.2 COUT26.1 COUT35.2 COUT36.2 COUT37.2 COUT38.2 COUT39.2 COUT40.2 COUT41.2 E2.1(A) E8.1(A) E21.1(A) J2.1(TP) J4.1(TP) J6.1(TP) J11.2 J11.3(GND_POWER) J11.4(GND_POWER) J11.5(GND_POWER) J12.2 J12.3(GND_POWER) J12.4(GND_POWER) J12.5(GND_POWER) J13.11(GND) J13.12(GND) J14.3(GND) J14.10(GND) J15.11(GND) J15.12(GND) J16.2(GND) JP4.3 Q21.2(S) Q26.2(S) R16.1 R81.2 R85.1 R96.1 R97.2 R98.1 R101.1 R102.1 R103.1(A) R103.2(WIPER) R104.2 R106.2 R107.1 R121.2 R129.1 R147.2 R163.2 R172.2 R176.1 R187.2 R191.1 R195.2 R201.2 R206.1 SW2.3 U1.42(PGND) U1.49(GND) U1.50(GND) U1.51(GND) U1.52(GND) U1.53(GND) U2.25(GND) U4.6(VPRG2) U4.7(VPRG1) U4.8(GND) U4.14(GND) U4.16(GND) U4.17(GND) U5.2(GND) U6.2(V-) U8.1(A0) U8.2(A1) U8.3(A2) U8.4(VSS) U8.7(WP) U15.5(PGND) U15.7(PGND) U15.8(PGND) U15.9(PGND) U15.20(PGND) U15.21(PGND) U15.22(PGND) U15.23(PGND) U15.24(PGND) U15.40(PGND) U16.5(PGND) U16.7(PGND) U16.8(PGND) U16.9(PGND) U16.20(PGND) U16.21(PGND) U16.22(PGND) U16.23(PGND) U16.24(PGND) U16.40(PGND) U17.5(PGND) U17.7(PGND) U17.8(PGND) U17.9(PGND) U17.20(PGND) U17.21(PGND) U17.22(PGND) U17.23(PGND) U17.24(PGND) U17.40(PGND) U18.5(PGND) U18.7(PGND) U18.8(PGND) U18.9(PGND) U18.20(PGND) U18.21(PGND) U18.22(PGND) U18.23(PGND) U18.24(PGND) U18.40(PGND)
GND_SIGNAL: C1.1 C7.1 C12.1 C13.1 C14.2 C17.2 C23.1 C204.2 C205.2 C206.2 C207.2 JP1.3 JP2.3 JP3.3 Q9.1(B) Q9.3(C) Q10.1(B) Q10.3(C) R23.2 R26.2 R28.2 R32.2 R36.2 R38.2 R55.1 R59.1
VDD25: C7.2 R22.1 R25.1 R27.1 R31.1 R35.1 R37.1 U1.26(VDD25)
VDD33: C1.2 C204.1 C205.1 C206.1 C207.1 D13.1(CATHODE) Q29.2(S) R6.2 R8.2 R9.2 R10.2 R11.1 R12.2 R13.1 R29.2 R34.2 U1.29(VDD33) U1.37(BOOST1) U1.44(BOOST0) U2.14(VCC1) U2.18(VCC0)
VIN: C2.1 C31.1 C52.1 C53.1 C54.1 E1.1(A) J1.1(TP) R1.1 R2.1 R4.2 R49.1 R123.1 R139.1 R159.1 U4.3(VIN)
VIN1: CIN1.1 CIN2.1 CIN3.1 CIN4.1 CIN5.1 CIN6.1 CIN7.1 CIN8.1 CIN9.1 CIN10.1 CIN11.1 CIN12.1 CIN13.1 CIN14.1 CIN15.1 CIN16.1 R1.2 R3.2 R159.2 U15.25(VIN) U15.26(VIN) U15.27(VIN) U15.28(VIN) U15.29(VIN) U15.30(VIN) U16.25(VIN) U16.26(VIN) U16.27(VIN) U16.28(VIN) U16.29(VIN) U16.30(VIN) U17.25(VIN) U17.26(VIN) U17.27(VIN) U17.28(VIN) U17.29(VIN) U17.30(VIN) U18.25(VIN) U18.26(VIN) U18.27(VIN) U18.28(VIN) U18.29(VIN) U18.30(VIN)
AC_DC: JP2.2 U2.22(LOWDCR)
ALERTB: E22.1(A) J13.3(ALERTB) J14.6(ALERTB) J15.3(ALERTB) Q20.1(G) R10.1 U1.15(ALERTB)
ASEL0: R22.2 R23.1 U1.20(ASEL0)
ASEL1: R25.2 R26.1 U1.21(ASEL1)
AUX3V4: D13.2(ANODE) J16.4(AUX3V4)
AUXVCC: C50.1 E36.1(A) J13.8(AUXP) J14.1(AUXP) J15.8(AUXP) R128.1 R150.1 U8.8(VCC)
EESCL: J14.11(AUXSCL) R128.2 U8.6(SCL)
EESDA: J14.12(AUXSDA) R150.2 U8.5(SDA)
EXTVCC: C6.2 C20.1 R87.2 U1.41(EXTVCC) U2.15(EXTVCC)
FAULT: D11.2(ANODE) E28.1(A) Q21.1(G) R29.1 R30.2 R138.2 U1.16(\\~{FAULT}0) U2.20(\\~{FAULT1}) U2.21(\\~{FAULT0})
FREQ_CFG: R35.2 R36.1 U1.24(FREQ_CFG)
ILIM: JP3.2 U2.10(ILIM)
INTVCC1: C4.2 R120.1 U1.39(INTVCC)
INTVCC2: C18.1 JP2.1 JP3.1 R56.2 R194.1 U2.16(INTVCC)
ITH: C12.2 C23.2 U1.7(ITH0) U1.30(ITH1) U2.8(ITH1) U2.23(ITH0)
PGOOD: E37.1(A) Q26.1(G) R34.1 U1.1(PGOOD0) U1.34(PGOOD1) U2.7(MODE1) U2.24(MODE0)
PHASE_CFG: R37.2 R38.1 U1.25(PHASE_CFG)
RUN: D11.1(CATHODE) E34.1(A) R8.1 R51.1 R52.1 R70.2 R137.2 R142.2 R211.2 R213.2 R215.2 R217.2 SW2.1 SW2.2 U1.18(RUN0) U1.19(RUN1)
SCL: E24.1(A) J13.6(SCL) J14.4(SCL) J15.6(SCL) J16.3(SCL) R12.1 U1.13(SCL)
SDA: E23.1(A) J13.4(SDA) J14.2(SDA) J15.4(SDA) J16.1(SDA) R11.2 U1.14(SDA)
SHARE_CLK: E25.1(A) R9.1 R127.1 U1.28(SHARE_CLK)
SW1: C29.2 R161.1 U15.32(PHASE)
SW2: C188.2 R170.1 U16.32(PHASE)
SW3: C194.2 R185.1 U17.32(PHASE)
SW4: C200.2 R200.1 U18.32(PHASE)
SYNC: E26.1(A) R13.2 R145.1 U1.12(SYNC) U2.11(SYNC)
VDR: C30.1 C41.2 C44.1 C51.1 C75.1 C190.1 C196.1 C202.1 L5.2 R87.1 R91.2 R94.1 R105.2 R164.2 R175.2 R190.2 R205.2 R212.2 R214.2 R216.2 R218.2 U15.4(VDRV) U16.4(VDRV) U17.4(VDRV) U18.4(VDRV)
VOUT: C34.1 C35.1 COUT1.1 COUT2.1 COUT3.1 COUT4.1 COUT5.1 COUT6.1 COUT7.1 COUT8.1 COUT9.1 COUT10.1 COUT11.1 COUT12.1 COUT13.1 COUT14.1 COUT15.1 COUT16.1 COUT17.1 COUT18.1 COUT19.1 COUT20.1 COUT22.1 COUT23.1 COUT24.1 COUT25.1 COUT26.2 COUT35.1 COUT36.1 COUT37.1 COUT38.1 COUT39.1 COUT40.1 COUT41.1 J3.1(TP) J5.1(TP) J11.1 L1.2 L2.2 L3.2 L4.2 Q23.2 Q24.2 R5.2 R85.2 R113.1 R114.1 R117.1 R125.2 R148.1 R174.2 R189.2 R204.2
VOUT0_CFG: R27.2 R28.1 U1.22(VOUT0_CFG)
VOUT1_CFG: R31.2 R32.1 U1.23(VOUT1_CFG)
VREF_CM1: C9.2 C16.2 C181.1 C186.1 R17.2 R24.2 R113.2 R114.2 R119.1 R120.2 R121.1 R167.1 R169.1 R181.1 U1.5(ISENSE1-) U1.9(ISENSE0-)
VREF_CM2: C21.2 C33.2 C192.1 C198.1 R117.2 R134.2 R141.2 R148.2 R184.1 R194.2 R195.1 R197.1 R199.1 R209.1 U2.2(ISENSE0-) U2.5(ISENSE1-)
VSENSE+: E3.1(A) R5.1 R124.2 R173.2 R188.2 R203.2 U1.2(VSENSE0+) U1.33(VSENSE1+)
VSENSE-: E4.1(A) R16.2 U1.3(VSENSE0-) U1.32(VSENSE1-)
WP1: JP1.2 R6.1 U1.27(WP)
N19055332: C3.2 R2.2 U1.40(VIN)
N19064724: C5.1 R3.1 U1.48(IIN-)
N19065153: C5.2 R4.1 U1.47(IIN+)
N19167019: C13.2 U1.6(ITH_R0) U1.31(ITH_R1)
N19178028: C17.1 Q9.2(E) U1.10(TSNS1)
N19241863: C14.1 Q10.2(E) U1.11(TSNS0)
N19417825: C9.1 C183.2 R14.2 R17.1 R119.2 R160.1 U1.8(ISENSE0+)
N19489859: C16.1 C187.2 R20.2 R24.1 R168.1 R169.2 U1.4(ISENSE1+)
N19517743: R30.1 U1.17(\\~{FAULT}1)
N19742939: C21.1 C199.2 R141.1 R143.2 R198.1 R199.2 U2.6(ISENSE1+)
N19758120: R52.2 U2.3(RUN0)
N19758540: R51.2 U2.4(RUN1)
N19769419: R55.2 U2.9(FREQ)
N19777670: R56.1 R59.2 U2.12(PHASMD)
N19792058: C33.1 C193.2 R134.1 R135.2 R183.1 R184.2 U2.1(ISENSE0+)
N19844769: C19.2 R49.2 U2.17(VIN)
N20479472: C40.2 R92.1 U6.1(VOUT)
N20479484: R95.1 R99.1 U6.3(+IN)
N20479490: C39.1 R95.2 U5.6(OUT) U6.5(V+)
N20479492: C42.2 J12.1 Q23.3 Q24.3 R100.2 R101.2 R102.2
N20479647: JP5.2 JP5.3 Q23.1 Q24.1 R89.2 R98.2
N20479673: JP5.1 R92.2
N20479683: E7.1(A) R89.1
N20479716: R94.2 R97.1 U5.4(DIV)
N20479804: R91.1 U5.5(V+)
N20479929: R93.1 R96.2 U5.1(MOD)
N20479960: C40.1 R100.1 U6.4(-IN)
N20480136: R99.2 R103.3(B) R104.1
N20480171: R93.2 U5.3(SET)
N20612248: L5.1 U4.1(SW)
N20614777: JP4.2 U4.5(RUN)
N20633357: C49.1 U4.10(SS)
N20641937: C51.2 R105.1 R107.2 U4.9(VFB)
N20657658: C43.1 R106.1 U4.11(ISET)
N20769646: L2.1 R20.1 U16.10(SW) U16.11(SW) U16.12(SW) U16.13(SW) U16.14(SW) U16.15(SW) U16.16(SW) U16.17(SW) U16.18(SW) U16.19(SW)
N20769684: L1.1 R14.1 U15.10(SW) U15.11(SW) U15.12(SW) U15.13(SW) U15.14(SW) U15.15(SW) U15.16(SW) U15.17(SW) U15.18(SW) U15.19(SW)
N20791829: L3.1 R135.1 U17.10(SW) U17.11(SW) U17.12(SW) U17.13(SW) U17.14(SW) U17.15(SW) U17.16(SW) U17.17(SW) U17.18(SW) U17.19(SW)
N20791866: L4.1 R143.1 U18.10(SW) U18.11(SW) U18.12(SW) U18.13(SW) U18.14(SW) U18.15(SW) U18.16(SW) U18.17(SW) U18.18(SW) U18.19(SW)
N20847944: D9.2(A) R130.2
N20847953: D9.1(K) Q26.3(D)
N20848126: J13.13(12V) J13.14(12V) J15.13(12V) J15.14(12V) R139.2
N20848139: J13.9(UNUSED) J15.9(UNUSED) R145.2
N20848161: J13.7(RESETB) J15.7(RESETB)
N20848163: J13.5(SHARE_CLK) J15.5(SHARE_CLK) R127.2
N20848169: J13.1(FAULTB) J15.1(FAULTB) R138.1 R142.1
N20848171: J13.10(UNUSED) J15.10(UNUSED) R151.2
N20848177: J13.2(CTRL) J15.2(CTRL) R122.2 R136.2 R137.1
N20848419: C28.1 R70.1
N20848573: J14.8(OUTEN_0) R122.1
N20848575: J14.9(OUTEN_1) R136.1
N20848628: Q29.1(G) R123.2 R147.1
N20849050: D6.2(A) R79.2
N20849078: D6.1(K) Q21.3(D)
N20849159: D7.2(A) Q20.3(D)
N20849178: D7.1(K) R81.1
N20952615: C29.1 R162.2
N20952619: C185.2 R164.1 U15.3(VCC)
N20952647: R160.2 U15.38(IOUT)
N20952684: C183.1 R161.2
N20952700: R124.1 R125.1 U15.1(VOS)
N20952702: U15.6(GL) U15.41(GL)
N20952718: R162.1 U15.33(BOOST)
N20952748: C184.1 U15.36(TOUT/FLT)
N20952777: R163.1 U15.37(OCSET)
N20953016: R129.2 U15.2(LGND)
N20953065: R43.2 U15.34(PWM)
N20953073: R211.1 R212.1 U15.35(EN)
N20954082: R43.1 U1.45(TG0)
N20954731: R167.2 U15.39(REFIN)
N20956606: C188.1 R171.2
N20956610: C191.2 R175.1 U16.3(VCC)
N20956638: R168.2 U16.38(IOUT)
N20956673: C187.1 R170.2
N20956685: R173.1 R174.1 U16.1(VOS)
N20956687: U16.6(GL) U16.41(GL)
N20956705: R171.1 U16.33(BOOST)
N20956729: C189.1 U16.36(TOUT/FLT)
N20956768: R172.1 U16.37(OCSET)
N20956995: R176.2 U16.2(LGND)
N20957049: R177.2 U16.34(PWM)
N20957060: R213.1 R214.1 U16.35(EN)
N20957084: R177.1 U1.36(TG1)
N20957140: R181.2 U16.39(REFIN)
N20961356: C194.1 R186.2
N20961360: C197.2 R190.1 U17.3(VCC)
N20961388: R183.2 U17.38(IOUT)
N20961423: C193.1 R185.2
N20961435: R188.1 R189.1 U17.1(VOS)
N20961437: U17.6(GL) U17.41(GL)
N20961455: R186.1 U17.33(BOOST)
N20961479: C195.1 U17.36(TOUT/FLT)
N20961518: R187.1 U17.37(OCSET)
N20961745: R191.2 U17.2(LGND)
N20961799: R192.2 U17.34(PWM)
N20961810: R215.1 R216.1 U17.35(EN)
N20961898: R197.2 U17.39(REFIN)
N20962359: R192.1 U2.19(PWM0)
N20963478: C200.1 R202.2
N20963493: C203.2 R205.1 U18.3(VCC)
N20963511: R198.2 U18.38(IOUT)
N20963554: C199.1 R200.2
N20963562: R203.1 R204.1 U18.1(VOS)
N20963564: U18.6(GL) U18.41(GL)
N20963586: R202.1 U18.33(BOOST)
N20963603: C201.1 U18.36(TOUT/FLT)
N20963647: R201.1 U18.37(OCSET)
N20963872: R206.2 U18.2(LGND)
N20963924: R207.2 U18.34(PWM)
N20963934: R217.1 R218.1 U18.35(EN)
N20963971: R209.2 U18.39(REFIN)
N20965242: R207.1 U2.13(PWM1)

Not connected (* = marked no-connect by the designer): J14 7(GPIO_1); JP1 1; JP4 1*; SW2 4 5 6; U1 35(SW1) 38(BG1) 43(BG0) 46(SW0); U4 12(FBO); U15 31(NC); U16 31(NC); U17 31(NC); U18 31(NC)

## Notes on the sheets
sheet 1
- 5.5V BIAS
- 27.4
- BIAS
- 2512
- ON
- OFF
- BLEEDER LOADS
- DYNAMIC LOAD CIRCUIT
- VOUT
- PULSE
- INT
- EXT
- 70Hz, 3% Duty Cycle
- IOUT STEP
- 1%
- HZ
sheet 2
- 7V - 14V
- FDMF3170
- FP1007R3-R22-R
- 1V/120A
- WP
- ON
- OFF
- FP1007R3-R22-R
- FDMF3170
- HZ
- NOTE:
  1. FDMF3170, FDMF3180, TDA21470 AND IR35412 ARE PIN COMPATIBLE
sheet 3
- FDMF3170
- FP1007R3-R22-R
- DCR SENSING
- LOWDCR
- NORMAL
- ILIM
- RANGE_HIGH
- RANGE_LOW
- FP1007R3-R22-R
- FDMF3170
- HZ
sheet 4
- ALL PARTS ON THIS PAGE ARE FOR DEMO BOARD ONLY, NOT NEEDED IN CUSTOMER DESIGN
- TO DC2086A
- RUN
- TO DC1613A
- ON
- OFF
- 1206
- PGOOD
- GPIO
- ALERTB
- HZ
